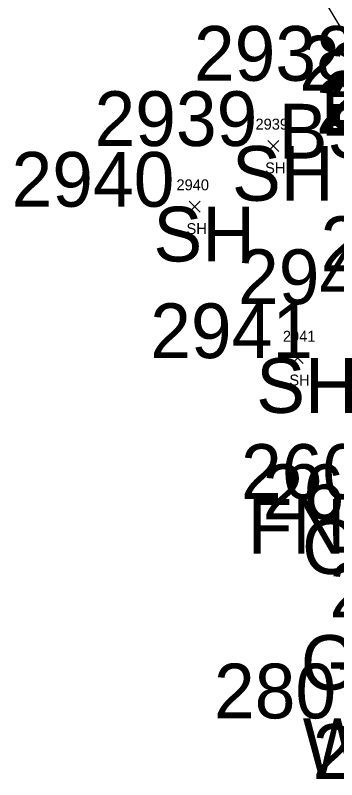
# Model space of a CAD drawing. Extents: x 1616840 to 1618410, y 488554 to 491945.
# Drawn here: x 1617192.8 to 1617251.5, y 491055.3 to 491195 of the extents above; entities that cross this region are included whole.
import ezdxf

# ---------------------------------------------------------------- set-up
doc = ezdxf.new("R2010")
doc.units = 0
for name, color, linetype in [('C_A', 7, 'Continuous'), ('C_I', 7, 'Continuous'), ('L_A', 7, 'Continuous'), ('L_I', 7, 'Continuous'), ('L_TIC', 7, 'Continuous'), ('LELB', 7, 'Continuous')]:
    doc.layers.add(name, color=color, linetype=linetype)

msp = doc.modelspace()

# ---------------------------------------------------------------- linework, layer by layer
at = {"layer": 'L_TIC'}
for points in [[(1617238.92, 491170.08), (1617240.92, 491172.08)], [(1617240.92, 491170.08), (1617238.92, 491172.08)], [(1617224.56, 491158.99), (1617226.56, 491160.99)], [(1617226.56, 491158.99), (1617224.56, 491160.99)], [(1617243.35, 491131.33), (1617245.35, 491133.33)], [(1617245.35, 491131.33), (1617243.35, 491133.33)]]:
    msp.add_lwpolyline(points, dxfattribs=at)
at = {"layer": 'LELB'}
msp.add_lwpolyline([(1617192.77, 491289.68), (1617214.76, 491256.37), (1617239.76, 491213.41), (1617258.01, 491183), (1617281.15, 491148.21), (1617286.6, 491120.54)], dxfattribs=at)
msp.add_lwpolyline([(1617192.77, 491289.68), (1617214.76, 491256.37), (1617239.76, 491213.41), (1617258.01, 491183), (1617281.15, 491148.21), (1617286.6, 491120.54)], dxfattribs=at)

# ---------------------------------------------------------------- texts
at = {"layer": 'C_A'}
for s, p in [('BS1', (1617248.56, 491173)), ('BS1 BS3 TS1', (1617240.89, 491168.79)), ('SH', (1617232.36, 491161.08)), ('SH', (1617218, 491149.99)), ('SH', (1617236.79, 491122.33)), ('FNBW ST', (1617235.23, 491096.62)), ('GARDEN', (1617245.17, 491092.91)), ('GARDEN ST', (1617244.94, 491071.73)), ('WELL', (1617245.29, 491056.52))]:
    msp.add_text(s, height=10, dxfattribs=at).set_placement(p)
at = {"layer": 'C_I'}
for s, p in [('2938', (1617225.41, 491183)), ('2817', (1617244.65, 491181.22)), ('2820', (1617250.16, 491180.01)), ('2816', (1617248.97, 491174.75)), ('2815', (1617247.7, 491173.31)), ('2939', (1617207.24, 491171.08)), ('2940', (1617192.09, 491159.99)), ('2943', (1617248.55, 491148.21)), ('2942', (1617233.46, 491142.2)), ('2941', (1617217.42, 491132.33)), ('2604', (1617234.01, 491106.62)), ('2603', (1617237.97, 491102.91)), ('2599', (1617250.17, 491084.96)), ('2807', (1617229.07, 491066.52)), ('2806', (1617247.12, 491055.46))]:
    msp.add_text(s, height=10, dxfattribs=at).set_placement(p)
at = {"layer": 'L_A'}
for p in [(1617238.41, 491166.08), (1617224.05, 491154.99), (1617242.84, 491127.33)]:
    msp.add_text('SH', height=2, dxfattribs=at).set_placement(p)
at = {"layer": 'L_I'}
for s, p in [('2939', (1617236.65, 491174.08)), ('2940', (1617222.21, 491162.99)), ('2941', (1617241.66, 491135.33))]:
    msp.add_text(s, height=2, dxfattribs=at).set_placement(p)

doc.saveas('drawing.dxf')
